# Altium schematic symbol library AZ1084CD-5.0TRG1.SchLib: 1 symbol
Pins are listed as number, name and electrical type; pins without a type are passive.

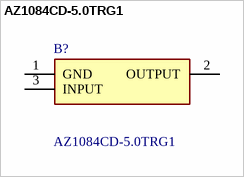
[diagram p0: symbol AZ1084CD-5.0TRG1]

## AZ1084CD-5.0TRG1
designator B?
Linear Voltage Regulator IC Positive Fixed 1 Output 5A TO-252-3; Manufacturer_Name: Diodes Incorporated; Geometry.Height: 2.527mm
footprint AZ1084CD50TRG1
pins: 1 GND, 2 OUTPUT, 3 INPUT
